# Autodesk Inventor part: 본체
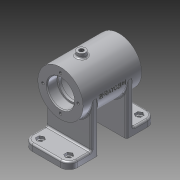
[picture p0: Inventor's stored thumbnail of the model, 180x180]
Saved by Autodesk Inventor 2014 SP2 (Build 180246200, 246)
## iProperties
Created: 2017-02
Part Number: 본체
Material: 알루미늄 6061
Document SubType Name: Modeling
Designer: 거성
Density: 2.71 g/cm^3
Appearance: 알루미늄 - 평지
Mass: 356.501 g
Surface Area: 422.83 cm^2
Volume: 131.55 cm^3
Author: 거성
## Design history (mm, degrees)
sketch "스케치1"
  geometry: C1 r 27 at (0, 0); 2 further points
  constraints: 2 coincident, 1 centre point
  dimensions: "d8" = 54 diameter of C1
extrude "돌출1" new body sketch "스케치1" stored distance "d9" = 70; taper "d10" = 0 deg
sketch "스케치2"
  geometry: C1 r 27 at (0, 0) reference; C2 r 16 at (0, 0)
  constraints: 1 centre point, 1 coincident
  dimensions: "d11" = 32 diameter of C2
extrude "돌출2" cut sketch "스케치2" distance "d12" = 12; taper "d13" = 0 deg
sketch "스케치3"
  geometry: C1 r 16 at (0, 0) reference; C2 r 14 at (0, 0)
  constraints: 1 centre point, 1 coincident
  dimensions: "d14" = 28 diameter of C2
extrude "돌출3" cut sketch "스케치3" distance "d15" = 3; taper "d16" = 0 deg
sketch "스케치4"
  geometry: C1 r 14 at (0, 0) reference; C2 r 22 at (0, 0)
  constraints: 1 centre point, 1 coincident
  dimensions: "d17" = 44 diameter of C2
extrude "돌출4" cut sketch "스케치4" distance "d18" = 40; taper "d19" = 0 deg
sketch "스케치5"
  geometry: C1 r 27 at (0, 0) reference; C2 r 16 at (0, 0)
  constraints: 1 centre point, 1 coincident
  dimensions: "d20" = 32 diameter of C2
extrude "돌출5" cut sketch "스케치5" distance "d21" = 12; taper "d22" = 0 deg
sketch "스케치6"
  geometry: C1 r 16 at (0, 0) reference; C2 r 14 at (0, 0)
  constraints: 1 centre point, 1 coincident
  dimensions: "d23" = 28 diameter of C2
extrude "돌출6" cut sketch "스케치6" distance "d24" = 3; taper "d25" = 0 deg
node "작업 평면1"
sketch "스케치7"
  geometry: L1 (27, -52)-(-27, -52); L2 (-27, -52)-(-27, -17); L3 (-27, -17)-(27, -17); L4 (27, -17)-(27, -52); 2 further points
  constraints: 8 end point, 2 parallel, 1 horizontal, 1 midpoint, 1 perpendicular, 1 vertical alignment
  dimensions: "d27" = 17 distance from line of L3 point (0, 0); "d28" = 52 distance from line of L1 point (0, 0); "d29" = 54 distance between parallel lines of L2 L4
extrude "돌출7" join sketch "스케치7" distance "d30" = 8; taper "d31" = 0 deg
sketch "스케치8"
  geometry: L1 (-27, 52)-(-27, 17) reference; L2 (-27, 25)-(27, 25); L3 (27, 25)-(27, 17); L4 (27, 17)-(-27, 17); L5 (-27, 17)-(-27, 25); 1 further point
  constraints: 8 end point, 2 parallel, 1 horizontal, 1 perpendicular, 1 point on line
  dimensions: "d32" = 8 distance between parallel lines of L2 L4
extrude "돌출8" join sketch "스케치8" stored distance "d33" = 8; taper "d34" = 0 deg
fillet "모깎기1" dims "d35" = 10
node "작업 평면2"
fillet "모깎기2" dims "d37" = 10
node "작업 평면3"
sketch "스케치9"
  geometry: L1 (27, 35)-(-27, 35) reference; C1 r 5 at (0, 10); 1 further point
  constraints: 1 centre point, 1 vertical alignment
  dimensions: "d39" = 10 diameter of C1; "d40" = 25 distance from line of L1 C1.centre
extrude "돌출9" join sketch "스케치9" stored distance "d41" = 8; taper "d42" = 0 deg
node "작업 평면4"
sketch "스케치10"
  geometry: L1 (0, 0)-(-16.339, -25.16); L2 (0, 0)-(30, 0)
  constraints: 4 end point, 1 equal length, 1 horizontal
  dimensions: "d44" = 30 distance of L1.start L1.end; "d45" = 123 deg angle of L1 L2
node "작업 평면5"
sketch "스케치11"
  geometry: C1 r 6 at (0, 0); 1 further point
  constraints: 1 centre point, 1 coincident
  dimensions: "d46" = 12 diameter of C1
extrude "돌출10" join sketch "스케치11" stored distance "d47" = 8; taper "d48" = 0 deg
sketch "스케치12"
  geometry: L1 (10, -21.5)-(6.103, -19.25); L2 (6.103, -19.25)-(6.103, -14.75); L3 (6.103, -14.75)-(10, -12.5); L4 (10, -12.5)-(13.897, -14.75); L5 (13.897, -14.75)-(13.897, -19.25); L6 (13.897, -19.25)-(10, -21.5); L7 (44, -12.5)-(47.897, -14.75); L8 (47.897, -14.75)-(47.897, -19.25); L9 (47.897, -19.25)-(44, -21.5); L10 (44, -21.5)-(40.103, -19.25); L11 (40.103, -19.25)-(40.103, -14.75); L12 (40.103, -14.75)-(44, -12.5); A1 r 10 centre (10, -17) between (0, -17) and (10, -27) reference; A2 r 10 centre (44, -17) between (44, -27) and (54, -17) reference; 3 further points
  constraints: 24 end point, 2 coincident, 2 vertical alignment, 26 other
  dimensions: "d49" = 9 distance of L1.start L3.end; "d50" = 9 distance of L7.start L9.end
extrude "돌출11" cut sketch "스케치12" distance "d51" = 3; taper "d52" = 0 deg
sketch "스케치13"
  geometry: C1 r 2.5 at (10, -17); C2 r 2.5 at (44, -17); A1 r 10 centre (10, -17) between (0, -17) and (10, -27) reference; A2 r 10 centre (44, -17) between (44, -27) and (54, -17) reference; 1 further point
  constraints: 2 centre point, 2 coincident
  dimensions: "d53" = 5 diameter of C1; "d54" = 5 diameter of C2
extrude "돌출12" cut sketch "스케치13" stored distance "d55" = 3; taper "d56" = 0 deg
sketch "스케치14" dims "d57" = 42
  geometry: L1 (0, 0)-(0, 21); C1 r 27 at (0, 0) reference
  constraints: 2 end point, 1 coincident, 1 vertical, 1 vertical alignment, 2 other
hole "구멍1" sketch "스케치14" at (0, 21) diameter "d58" = 3.242; stored, may be unused: countersink angle "d62" = 90 deg, drill point angle "d64" = 118 deg; dims "d59" = 8, "d60" = 4, "d61" = 2, "d63" = 10
hole "구멍2" diameter "d70" = 5.188; stored, may be unused: countersink angle "d74" = 90 deg, drill point angle "d76" = 118 deg; dims "d68" = 10, "d69" = 10, "d71" = 19, "d72" = 4, "d73" = 2, "d75" = 20
hole "구멍3" diameter "d79" = 5.188; stored, may be unused: countersink angle "d83" = 90 deg, drill point angle "d85" = 118 deg; dims "d77" = 10, "d78" = 10, "d80" = 19, "d81" = 4, "d82" = 2, "d84" = 20
fillet "모깎기3" dims "d86" = 2
node "작업 평면6"
sketch "스케치15"
  geometry: L1 (27, 35)-(-27, 35) reference; L2 (27, -35)-(27, 35) reference; 2 further points
  constraints: 1 other
  dimensions: "d87" = 35 distance from line of L1 point (0, 0); "d88" = 27 distance from line of L2 point (0, 0)
feature "엠보싱1" sketch "스케치15" dims "d8" = 54, "d17" = 44, "d89" = 0.5, "d90" = 0
chamfer "모따기1" distance "d91" = 1; stored, may be unused: second distance "d92" = 2, angle "d93" = 45 deg
fillet "모깎기4" dims "d94" = 3
fillet "모깎기5" dims "d95" = 0.3
node "솔리드1"
mirror "대칭1"
mirror "대칭2"
pattern_circular "원형 패턴1" dims angle "d66" = 360 deg
mirror "대칭3"
other parameters: "d36" = 0, "d38" = 32, "d43" = -35
